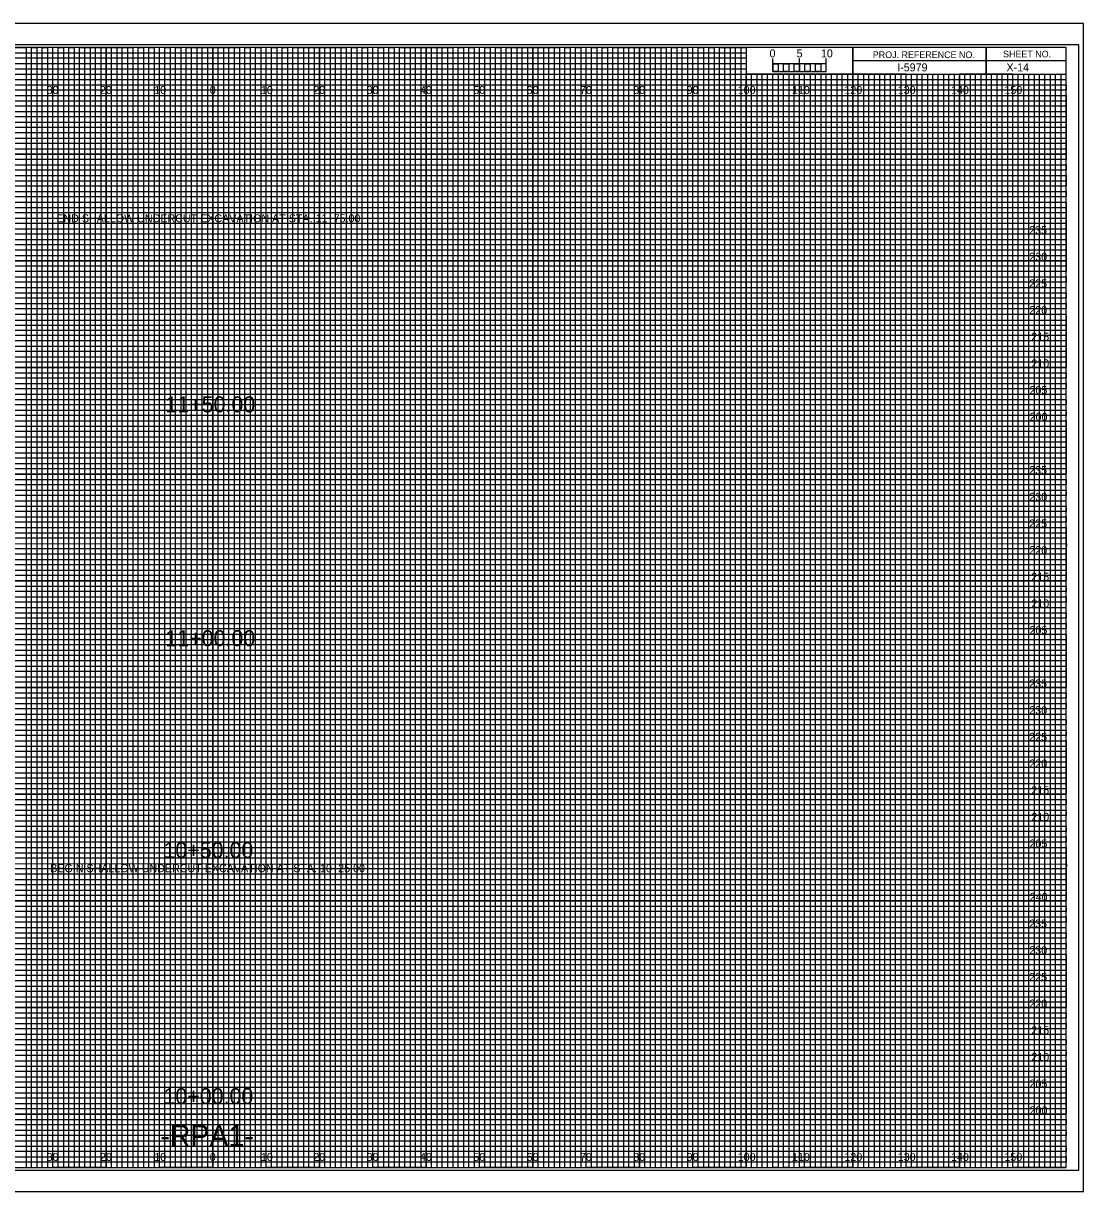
# Model space of a CAD drawing. Extents: x -13 to 323, y -5 to 654.
# Drawn here: x 124.5 to 323.3, y -4.5 to 214.5 of the extents above; entities that cross this region are included whole.
import ezdxf

# ---------------------------------------------------------------- set-up
doc = ezdxf.new("R2010")
doc.units = 0
for name, color, linetype in [('Prop XS Alignment Label', 7, 'Continuous'), ('Prop XS Bar Scale Labels', 7, 'Continuous'), ('Prop XS Elevation Labels', 7, 'Continuous'), ('Prop XS Hydro Elevations', 7, 'Continuous'), ('Prop XS Offset Labels', 7, 'Continuous'), ('Prop XS Project Number', 7, 'Continuous'), ('Prop XS Sheet Number', 7, 'Continuous'), ('Prop XS Station Labels', 7, 'Continuous'), ('Sheet Cross Section CELL', 7, 'Continuous'), ('Sheet Cross Section Grid Major CELL', 7, 'Continuous'), ('Sheet Cross Section Grid Middle CELL', 7, 'Continuous'), ('Sheet Cross Section Grid Minor 1 CELL', 7, 'Continuous'), ('Sheet Cross Section Grid Minor 2 CELL', 7, 'Continuous'), ('Sheet Cross Section Scale CELL', 7, 'Continuous'), ('Sheet Cutting Line CELL', 7, 'Continuous'), ('Sheet DOT Grid CELL', 7, 'Continuous'), ('Sheet Plot Border Inside CELL', 7, 'Continuous'), ('Sheet Plot Border Outside CELL', 7, 'Continuous')]:
    doc.layers.add(name, color=color, linetype=linetype)

msp = doc.modelspace()

# ---------------------------------------------------------------- linework, layer by layer
at = {"layer": 'Sheet Cross Section CELL'}
for p, q in [((305, 210), (305, 205)), ((305, 205), (305, 210)), ((280, 207.5), (280, 205)), ((320, 207.49), (280, 207.49)), ((280, 205), (320, 205))]:
    msp.add_line(p, q, dxfattribs=at)
for points in [[(320, 210), (0, 210), (0, 0), (320, 0)], [(280, 210), (260, 210), (260, 205.03), (280, 205.03)], [(320, 210), (280, 210), (280, 205), (320, 205)]]:
    msp.add_lwpolyline(points, close=True, dxfattribs=at)
at = {"layer": 'Sheet Cross Section Grid Major CELL'}
for p, q in [((130, 210), (120, 210)), ((130, 0), (130, 210)), ((150, 210), (140, 210)), ((140, 210), (140, 0)), ((150, 0), (150, 210)), ((170, 210), (160, 210)), ((160, 210), (160, 0)), ((170, 0), (170, 210)), ((190, 210), (180, 210)), ((180, 210), (180, 0)), ((190, 0), (190, 210)), ((210, 210), (200, 210)), ((200, 210), (200, 0)), ((210, 0), (210, 210)), ((230, 210), (220, 210)), ((220, 210), (220, 0)), ((230, 0), (230, 210)), ((250, 210), (240, 210)), ((240, 210), (240, 0)), ((250, 0), (250, 210)), ((260, 210), (260, 0)), ((270, 0), (270, 205)), ((290, 205), (280, 205)), ((280, 205), (280, 0)), ((290, 0), (290, 205)), ((310, 205), (300, 205)), ((300, 205), (300, 0)), ((310, 0), (310, 205)), ((140, 0), (130, 0)), ((160, 0), (150, 0)), ((180, 0), (170, 0)), ((200, 0), (190, 0)), ((220, 0), (210, 0)), ((240, 0), (230, 0)), ((260, 0), (250, 0)), ((280, 0), (270, 0)), ((300, 0), (290, 0)), ((320, 0), (310, 0)), ((320, 0), (320, 0))]:
    msp.add_line(p, q, dxfattribs=at)
for points in [[(0, 200), (320, 200), (320, 190), (0, 190)], [(0, 180), (320, 180), (320, 170), (0, 170)], [(0, 160), (320, 160), (320, 150), (0, 150)], [(0, 140), (320, 140), (320, 130), (0, 130)], [(0, 120), (320, 120), (320, 110), (0, 110)], [(0, 100), (320, 100), (320, 90), (0, 90)], [(0, 80), (320, 80), (320, 70), (0, 70)], [(0, 60), (320, 60), (320, 50), (0, 50)], [(0, 40), (320, 40), (320, 30), (0, 30)], [(0, 20), (320, 20), (320, 10), (0, 10)]]:
    msp.add_lwpolyline(points, dxfattribs=at)
at = {"layer": 'Sheet Cross Section Grid Middle CELL'}
for points in [[(115, 210), (125, 210), (125, 0), (135, 0), (135, 210), (145, 210), (145, 0), (155, 0), (155, 210), (165, 210), (165, 0), (175, 0), (175, 210), (185, 210), (185, 0), (195, 0), (195, 210), (205, 210), (205, 0), (215, 0), (215, 210), (225, 210), (225, 0), (235, 0), (235, 210), (245, 210), (245, 0), (255, 0), (255, 210), (259.93, 210), (260, 210), (260, 205), (264.99, 205), (264.99, 0), (275, 0), (275, 205), (285, 205), (285, 0), (295, 0), (295, 205), (305, 205), (305, 0), (315, 0), (315, 205)], [(0, 205), (275, 205)], [(0, 185), (320, 185), (320, 195), (0, 195)], [(0, 165), (320, 165), (320, 175), (0, 175)], [(0, 145), (320, 145), (320, 155), (0, 155)], [(0, 125), (320, 125), (320, 135), (0, 135)], [(0, 105), (320, 105), (320, 115), (0, 115)], [(0, 85), (320, 85), (320, 95), (0, 95)], [(0, 65), (320, 65), (320, 75), (0, 75)], [(0, 45), (320, 45), (320, 55), (0, 55)], [(0, 25), (320, 25), (320, 35), (0, 35)], [(0, 5), (320, 5), (320, 15), (0, 15)]]:
    msp.add_lwpolyline(points, dxfattribs=at)
at = {"layer": 'Sheet Cross Section Grid Minor 1 CELL'}
for p, q in [((0, 209), (260, 209)), ((260, 209), (260, 207.98)), ((260, 207.98), (0, 207.98)), ((0, 207), (260, 207)), ((260, 205.89), (0, 205.89)), ((260, 207), (260, 205.89)), ((0, 204), (320, 204))]:
    msp.add_line(p, q, dxfattribs=at)
for points in [[(0, 203), (270, 203), (320, 203), (320, 202), (0, 202)], [(0, 201), (320, 201), (320, 199), (0, 199)], [(0, 198), (320, 198), (320, 197), (0, 196.98)], [(0, 196), (320, 196), (320, 194), (0, 194)], [(0, 193), (320, 193), (320, 192), (0, 192)], [(0, 191), (320, 191), (320, 189), (0, 189)], [(0, 188), (320, 188), (320, 187), (0, 187)], [(0, 186), (320, 186), (320, 184), (0, 184)], [(0, 183), (320, 183), (320, 182), (0, 182)], [(0, 181), (320, 181), (320, 179), (0, 179)], [(0, 178), (320, 178), (320, 177), (0, 177)], [(0, 176), (320, 176), (320, 173.95), (320, 173), (320, 172), (0, 172)], [(0, 174), (320, 174), (320, 173), (0, 173)], [(0, 171), (320, 171), (320, 169), (0, 169.03)], [(0, 169.03), (320, 169), (320, 168), (0, 168)], [(0, 167), (320, 167), (320, 166), (0, 166)], [(0, 164), (320, 164), (320, 163), (0, 163)], [(0, 162), (320, 162), (320, 161), (0, 161)], [(-0.07, 158.89), (320, 158.89), (320, 157.88), (-0.07, 157.88)], [(0, 157), (320, 157), (320, 156), (0, 156)], [(0, 154), (320, 154), (320, 153), (0, 153)], [(0, 152), (320, 152), (320, 151), (0, 151)], [(0, 149), (320, 149), (320, 148), (0, 148)], [(0, 147), (320, 147), (320, 146), (0, 146)], [(0, 144), (320, 144), (320, 143), (0, 143)], [(0, 142), (320, 142), (320, 141), (0, 141)], [(0, 139), (320, 139), (319.99, 137.98), (0, 138)], [(0, 137), (320, 137), (320, 136), (0, 136)], [(0, 134), (320, 134), (320, 133), (0, 133)], [(0, 132), (320, 132), (320, 131), (0, 131)], [(0, 129), (320, 129), (320, 128), (0, 128)], [(0, 127), (320, 127), (320, 126), (0, 126)], [(0, 124), (320, 124), (320, 123), (0, 123)], [(0, 122), (320, 122), (320, 121), (0, 121)], [(0, 119), (320, 119), (320, 118), (0, 118)], [(0, 116.99), (320.07, 116.91), (320, 116), (0, 116)], [(0, 114), (320, 114), (320, 113), (0, 113)], [(0, 112), (320, 112), (320, 111), (0, 111)], [(0, 109), (320, 109), (320, 108), (0, 108)], [(0, 107), (320, 107), (320, 106), (0, 106)], [(0, 104), (320, 104), (320, 103), (0, 103)], [(0, 102), (320, 102), (320, 101), (0, 101)], [(0, 99), (320, 99), (320, 98), (0, 98)], [(0, 97), (320, 97), (320, 96), (0, 96)], [(0, 94), (320, 94), (320, 93), (0, 93)], [(0, 92), (320, 92), (320, 91), (0, 91)], [(0, 89), (320, 89), (320, 88), (0, 88)], [(0, 87), (320, 87), (320, 86), (0, 86)], [(0, 84), (320, 84), (320, 83), (0, 83)], [(0, 82), (320, 82), (320, 81), (0, 81)], [(0, 79), (320, 79), (319.99, 77.98), (0, 78)], [(0, 77), (320, 77), (320, 76), (0, 76)], [(0, 74), (320, 74), (320, 73), (0, 73)], [(0, 72), (320, 72), (320, 71), (0, 71)], [(0, 69), (320, 69), (320, 68), (0, 68)], [(0, 67), (320, 67), (320, 66), (0, 66)], [(0, 64), (320, 64), (320, 63), (0, 63)], [(0, 62), (320, 62), (320, 61), (0, 61)], [(0, 59), (320, 59), (320, 58), (0, 58)], [(0, 56.99), (320.07, 56.91), (320, 56), (0, 56)], [(0, 54), (320, 54), (320, 53), (0, 53)], [(0, 52), (320, 52), (320, 51), (0, 51)], [(0, 49), (320, 49), (320, 48), (0, 48)], [(0, 47), (320, 47), (320, 46), (0, 46)], [(0, 44), (320, 44), (320, 43), (0, 43)], [(0, 42), (320, 42), (320, 41), (0, 41)], [(0, 39), (320, 39), (320, 38), (0, 38)], [(0, 37), (320, 37), (320, 36), (0, 36)], [(0, 34), (320, 34), (320, 33), (0, 33)], [(0, 32), (320, 32), (320, 31), (0, 31)], [(0, 29), (320, 29), (320, 28), (0, 28)], [(0, 27), (320, 27), (320, 26), (0, 26)], [(0, 24), (320, 24), (320, 23), (0, 23)], [(0, 22), (320, 22), (320, 21), (0, 21)], [(0, 19), (320, 19), (320, 18), (0, 18)], [(0, 17), (320, 17), (320, 16), (0, 16)], [(0, 14), (320, 14), (320, 13), (0, 13)], [(0, 12), (320, 12), (320, 11), (0, 11)], [(0, 9), (320, 9), (320, 8), (0, 8)], [(0, 7), (320, 7), (320, 6), (0, 6)], [(0, 4), (320, 4), (320, 3), (0, 3)], [(0, 2), (320, 2), (320, 1), (0, 1)]]:
    msp.add_lwpolyline(points, dxfattribs=at)
at = {"layer": 'Sheet Cross Section Grid Minor 2 CELL'}
for p, q in [((267, 205), (266.01, 205)), ((266.01, 205), (266.01, 0)), ((267, 0), (267, 205)), ((269, 205), (268, 205)), ((268, 205), (268, 0)), ((269, 0), (269, 205)), ((266.01, 0), (265, 0)), ((268, 0), (267, 0))]:
    msp.add_line(p, q, dxfattribs=at)
for points in [[(125, 0), (126, 0), (126, 210), (127, 210), (127, 0)], [(127, 0), (128, 0), (128, 210), (129, 210), (129, 0)], [(130, 0), (131, 0), (131, 210), (132, 210), (132, 0)], [(132, 0), (133, 0), (133, 210), (134, 210), (134, 0)], [(135, 0), (136, 0), (136, 210), (137, 210), (137, 0)], [(137, 0), (138, 0), (138, 210), (139, 210), (139, 0)], [(140, 0), (141, 0), (141, 210), (142, 210), (142, 0)], [(142, 0), (143, 0), (143, 210), (144, 210), (144, 0)], [(145, 0), (146, 0), (146, 210), (147, 210), (147, 0)], [(147, 0), (148, 0), (148, 210), (149, 210), (149, 0)], [(150, 0), (151, 0), (151, 210), (152, 210), (152, 0)], [(152, 0), (153, 0), (153, 210), (154, 210), (154, 0)], [(155, 0), (156, 0), (156, 210), (157, 210), (157, 0)], [(157, 0), (158, 0), (158, 210), (159, 210), (159, 0)], [(160, 0), (161, 0), (161, 210), (162, 210), (162, 0)], [(162, 0), (163, 0), (163, 210), (164, 210), (164, 0)], [(165, 0), (166, 0), (166, 210), (167, 210), (167, 0)], [(167, 0), (168, 0), (168, 210), (169, 210), (169, 0)], [(170, 0), (171, 0), (171, 210), (172, 210), (172, 0)], [(172, 0), (173, 0), (173, 210), (174, 210), (174, 0)], [(175, 0), (176, 0), (176, 210), (177, 210), (177, 0)], [(177, 0), (178, 0), (178, 210), (179, 210), (179, 0)], [(180, 0), (181, 0), (181, 210), (182, 210), (182, 0)], [(182, 0), (183, 0), (183, 210), (184, 210), (184, 0)], [(185, 0), (186, 0), (186, 210), (187, 210), (187, 0)], [(187, 0), (188, 0), (188, 210), (189, 210), (189, 0)], [(190, 0), (191, 0), (191, 210), (192, 210), (192, 0)], [(192, 0), (193, 0), (193, 210), (194, 210), (194, 0)], [(195, 0), (196, 0), (196, 210), (197, 210), (197, 0)], [(197, 0), (198, 0), (198, 210), (199, 210), (199, 0)], [(200, 0), (201, 0), (201, 210), (202, 210), (202, 0)], [(202, 0), (203, 0), (203, 210), (204, 210), (204, 0)], [(205, 0), (206, 0), (206, 210), (207, 210), (207, 0)], [(207, 0), (208, 0), (208, 210), (209, 210), (209, 0)], [(210, 0), (211, 0), (211, 210), (212, 210), (212, 0)], [(212, 0), (213, 0), (213, 210), (214, 210), (214, 0)], [(215, 0), (216, 0), (216, 210), (217, 210), (217, 0)], [(217, 0), (218, 0), (218, 210), (219, 210), (219, 0)], [(220, 0), (221, 0), (221, 210), (222, 210), (222, 0)], [(222, 0), (223, 0), (223, 210), (224, 210), (224, 0)], [(225, 0), (226, 0), (226, 210), (227, 210), (227, 0)], [(227, 0), (228, 0), (228, 210), (229, 210), (229, 0)], [(230, 0), (231, 0), (231, 210), (232, 210), (232, 0)], [(232, 0), (233, 0), (233, 210), (234, 210), (234, 0)], [(235, 0), (236, 0), (236, 210), (237, 210), (237, 0)], [(237, 0), (238, 0), (238, 210), (239, 210), (239, 0)], [(240, 0), (241, 0), (241, 210), (242, 210), (242, 0)], [(242, 0), (243, 0), (243, 210), (244, 210), (244, 0)], [(245, 0), (246, 0), (246, 210), (247, 210), (247, 0)], [(247, 0), (248, 0), (248, 210), (249, 210), (249, 0)], [(250, 0), (251, 0), (251, 210), (252, 210), (252, 0)], [(252, 0), (253, 0), (253, 210), (254, 210), (254, 0)], [(255, 0), (256, 0), (256, 210), (257, 210), (257, 0)], [(257, 0), (258, 0), (258, 210), (259, 210), (259, 0)], [(260, 0), (261, 0), (261, 205), (262.02, 205), (262.02, 0)], [(262, 0), (263, 0), (263, 205), (263.99, 205), (263.99, 0)], [(270, 0), (270.98, 0), (270.98, 205), (272, 205), (272, 0)], [(272, 0), (273, 0), (273, 205), (274.05, 205), (274.05, 0)], [(275, 0), (276, 0), (276, 205), (277, 205), (277, 0)], [(277, 0), (278, 0), (278, 205), (279, 205), (279, 0)], [(280, 0), (281, 0), (281, 205), (282, 205), (282, 0)], [(282, 0), (283, 0), (283, 205), (284, 205), (284, 0)], [(285, 0), (286, 0), (286, 205), (287, 205), (287, 0)], [(287, 0), (288, 0), (288, 205), (289, 205), (289, 0)], [(290, 0), (291, 0), (291, 205), (292, 205), (292, 0)], [(292, 0), (293, 0), (293, 205), (294, 205), (294, 0)], [(295, 0), (296, 0), (296, 205), (297, 205), (297, 0)], [(297, 0), (298, 0), (298, 205), (299, 205), (299, 0)], [(300, 0), (301, 0), (301, 205), (302, 205), (302, 0)], [(302, 0), (303, 0), (303, 205), (304, 205), (304, 0)], [(305, 0), (306, 0), (306, 205), (307, 205), (307, 0)], [(307, 0), (308, 0), (308, 205), (309, 205), (309, 0)], [(310, 0), (311, 0), (311, 205), (312, 205), (312, 0)], [(312, 0), (313, 0), (313, 205), (314, 205), (314, 0)], [(315, 0), (316, 0), (316, 205), (317, 205), (317, 0)], [(317, 0), (318, 0), (318, 205), (319, 205), (319, 0)]]:
    msp.add_lwpolyline(points, dxfattribs=at)
at = {"layer": 'Sheet Cross Section Scale CELL'}
for p, q in [((265, 205.49), (265, 207.9)), ((265, 206.9), (265, 207.9)), ((270, 205.49), (270, 207.9)), ((275, 205.49), (275, 207.9)), ((275, 206.9), (275, 207.9))]:
    msp.add_line(p, q, dxfattribs=at)
for points in [[(275, 206.9), (265, 206.9), (265, 205.49), (275, 205.49)], [(265, 206.9), (266, 206.9), (266, 205.49), (265, 205.49)], [(267, 206.9), (268, 206.9), (268, 205.49), (267, 205.49)], [(269, 206.9), (270, 206.9), (270, 205.49), (269, 205.49)], [(271, 206.9), (272, 206.9), (272, 205.49), (271, 205.49)], [(273, 206.9), (274, 206.9), (274, 205.49), (273, 205.49)]]:
    msp.add_lwpolyline(points, close=True, dxfattribs=at)
at = {"layer": 'Sheet Cutting Line CELL'}
for p, q in [((323.3, 214.5), (-13.4, 214.5)), ((-13.4, -4.5), (323.3, -4.5))]:
    msp.add_line(p, q, dxfattribs=at)
at = {"layer": 'Sheet DOT Grid CELL'}
for p, q in [((130, 0), (130, 210)), ((140, 0), (140, 210)), ((150, 0), (150, 210)), ((160, 0), (160, 210)), ((170, 0), (170, 210)), ((180, 0), (180, 210)), ((190, 0), (190, 210)), ((200, 0), (200, 210)), ((210, 0), (210, 210)), ((220, 0), (220, 210)), ((230, 0), (230, 210)), ((240, 0), (240, 210)), ((250, 0), (250, 210)), ((260, 0), (260, 204.69)), ((270, 0), (270, 204.69)), ((280, 0), (280, 204.69)), ((290, 0), (290, 204.69)), ((300, 0), (300, 204.69)), ((310, 0), (310, 204.69)), ((0, 200), (320, 200)), ((0, 190), (320, 190)), ((0, 180), (320, 180)), ((0, 170), (320, 170)), ((0, 160), (320, 160)), ((0, 150), (320, 150)), ((0, 140), (320, 140)), ((0, 130), (320, 130)), ((0, 120), (320, 120)), ((0, 110), (320, 110)), ((0, 100), (320, 100)), ((0, 90), (320, 90)), ((0, 80), (320, 80)), ((0, 70), (320, 70)), ((0, 60), (320, 60)), ((0, 50), (320, 50)), ((0, 40), (320, 40)), ((0, 30), (320, 30)), ((0, 20), (320, 20)), ((0, 10), (320, 10))]:
    msp.add_line(p, q, dxfattribs=at)
at = {"layer": 'Sheet Plot Border Inside CELL'}
msp.add_lwpolyline([(-10.8, -0.5), (322.4, -0.5), (322.4, 210.5), (-10.8, 210.5)], close=True, dxfattribs=at)
at = {"layer": 'Sheet Plot Border Outside CELL'}
msp.add_lwpolyline([(-13.4, -4.5), (323.3, -4.5), (323.3, 214.5), (-13.4, 214.5)], close=True, dxfattribs=at)

# ---------------------------------------------------------------- texts
at = {"layer": 'Prop XS Alignment Label'}
msp.add_text('-RPA1-', height=4, dxfattribs=at).set_placement((150.18, 4))
at = {"layer": 'Prop XS Bar Scale Labels'}
for s, p in [('5', (269.47, 208.12)), ('10', (274.04, 208.12))]:
    msp.add_text(s, height=1.5, dxfattribs=at).set_placement(p)
at = {"layer": 'Prop XS Elevation Labels'}
for s, p in [('235', (313.09, 175)), ('230', (313.11, 170)), ('225', (313.1, 165)), ('220', (313.12, 160)), ('215', (313.48, 155)), ('210', (313.5, 150)), ('205', (313.15, 145)), ('200', (313.17, 140)), ('235', (313.09, 130)), ('230', (313.11, 125)), ('225', (313.1, 120)), ('220', (313.12, 115)), ('215', (313.48, 110)), ('210', (313.5, 105)), ('205', (313.15, 100)), ('235', (313.09, 90)), ('230', (313.11, 85)), ('225', (313.1, 80)), ('220', (313.12, 75)), ('215', (313.48, 70)), ('210', (313.5, 65)), ('205', (313.15, 60)), ('240', (313.19, 50)), ('235', (313.09, 45)), ('230', (313.11, 40)), ('225', (313.1, 35)), ('220', (313.12, 30)), ('215', (313.48, 25)), ('210', (313.5, 20)), ('205', (313.15, 15)), ('200', (313.17, 10))]:
    msp.add_text(s, height=1.5, dxfattribs=at).set_placement(p)
at = {"layer": 'Prop XS Hydro Elevations'}
for s, p in [('END SHALLOW UNDERCUT EXCAVATION AT STA. 11+75.00', (130.68, 177.21)), ('BEGIN SHALLOW UNDERCUT EXCAVATION AT STA. 10+25.00', (129.53, 55.38))]:
    msp.add_text(s, height=1.5, dxfattribs=at).set_placement(p)
at = {"layer": 'Prop XS Offset Labels'}
for s, p in [('30', (128.86, 201.25)), ('20', (138.86, 201.25)), ('10', (149.04, 201.25)), ('0', (159.45, 201.25)), ('0', (159.45, 201.25)), ('10', (169.04, 201.25)), ('20', (178.86, 201.25)), ('30', (188.86, 201.25)), ('40', (198.86, 201.25)), ('50', (208.86, 201.25)), ('60', (218.86, 201.25)), ('70', (228.86, 201.25)), ('80', (238.86, 201.25)), ('90', (248.86, 201.25)), ('100', (258.44, 201.25)), ('110', (268.62, 201.25)), ('120', (278.44, 201.25)), ('130', (288.44, 201.25)), ('140', (298.44, 201.25)), ('150', (308.44, 201.25)), ('30', (128.86, 1.25)), ('20', (138.86, 1.25)), ('10', (149.04, 1.25)), ('0', (159.45, 1.25)), ('0', (159.45, 1.25)), ('10', (169.04, 1.25)), ('20', (178.86, 1.25)), ('30', (188.86, 1.25)), ('40', (198.86, 1.25)), ('50', (208.86, 1.25)), ('60', (218.86, 1.25)), ('70', (228.86, 1.25)), ('80', (238.86, 1.25)), ('90', (248.86, 1.25)), ('100', (258.44, 1.25)), ('110', (268.62, 1.25)), ('120', (278.44, 1.25)), ('130', (288.44, 1.25)), ('140', (298.44, 1.25)), ('150', (308.44, 1.25))]:
    msp.add_text(s, height=1.5, dxfattribs=at).set_placement(p)
at = {"layer": 'Prop XS Project Number'}
msp.add_text('I-5979', height=1.5, dxfattribs=at).set_placement((288.34, 205.5))
at = {"layer": 'Prop XS Sheet Number'}
msp.add_text('X-14', height=1.5, dxfattribs=at).set_placement((308.83, 205.5))
at = {"layer": 'Prop XS Station Labels'}
for s, p in [('11+50.00', (151.13, 141.58)), ('11+00.00', (151.13, 97.75)), ('10+50.00', (150.77, 58.03)), ('10+00.00', (150.77, 11.91))]:
    msp.add_text(s, height=3, dxfattribs=at).set_placement(p)
at = {"layer": 'Sheet Cross Section CELL'}
for s, p in [('PROJ. REFERENCE NO.', (283.77, 207.99)), ('SHEET NO.', (308.19, 208.12))]:
    msp.add_text(s, height=1.25, dxfattribs=at).set_placement(p)
at = {"layer": 'Sheet Cross Section Scale CELL'}
msp.add_text('0', height=1.5, dxfattribs=at).set_placement((264.41, 208.12))

doc.saveas('drawing.dxf')
